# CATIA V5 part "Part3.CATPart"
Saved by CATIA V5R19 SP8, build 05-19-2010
Part number: Scie
Bounding box of the stored display mesh (mm): x 6.498 to 6.498, y -330 to 330, z -245 to -190
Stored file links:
  G:\EU_thinkMotion\CFAO_2010\MMS_groupe1\MMS_groupe1\OK\ppiault\piault\piault_cfao\Part3.CATPart
  D:\Catia\Finaltest.CATProduct
  G:\EU_thinkMotion\CFAO_2010\MMS_groupe1\MMS_groupe1\OK\ppiault\piault\piault_cfao\Part2.CATPart
  G:\Catia Projet\CFAO2\Product2.CATProduct
  G:\EU_thinkMotion\CFAO_2010\MMS_groupe1\MMS_groupe1\OK\ppiault\piault\piault_cfao\Part1.CATPart
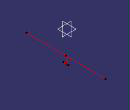
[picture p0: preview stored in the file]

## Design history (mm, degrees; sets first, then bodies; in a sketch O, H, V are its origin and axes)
External parameters (linked from other documents)
  External.DiametreScie = 330 mm
Set1
  Point1 to Point3: linked copy from another document
Set2
  Line1: type PtDir, RefPoint Point2, Direction zx-plane, Start 330 {= External.DiametreScie}, End -330 {= -External.DiametreScie}
  Line2: type PtPt, FirstPoint Point3, SecondPoint Point2
  Line3: type PtDir, RefPoint Point3, Direction zx-plane, Start -20, End 20
Body1 (main body)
